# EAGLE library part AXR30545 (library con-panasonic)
AXR30545 Plug (Board mounting type) B type Source: http://www.panasonic-electric-works.ch/home/www/catalogues/connector/download/en_ds_65201_0000.pdf
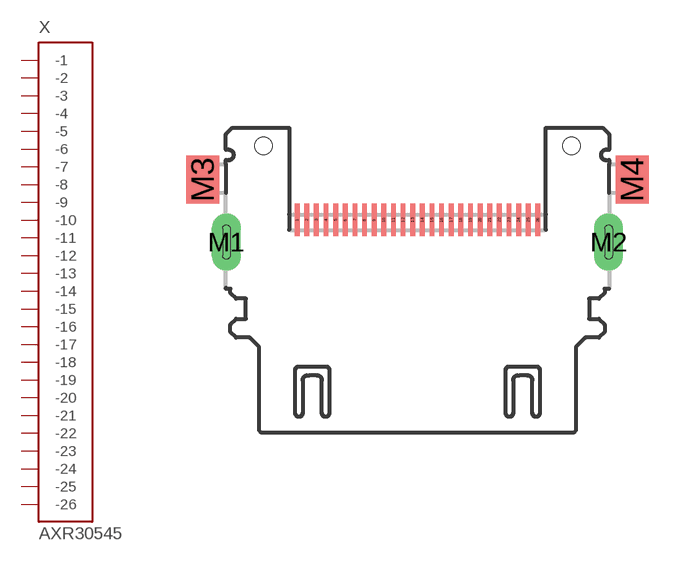
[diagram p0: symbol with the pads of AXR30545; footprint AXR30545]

Designator prefix X

## AXR30545  [AXR30545]
1  -1  in
2  -2  in
3  -3  in
4  -4  in
5  -5  in
6  -6  in
7  -7  in
8  -8  in
9  -9  in
10  -10  in
11  -11  in
12  -12  in
13  -13  in
14  -14  in
15  -15  in
16  -16  in
17  -17  in
18  -18  in
19  -19  in
20  -20  in
21  -21  in
22  -22  in
23  -23  in
24  -24  in
25  -25  in
26  -26  in

## Footprint AXR30545 (pad centres in mm)
AXR30545 Connector Source: http://www.panasonic-electric-works.ch/home/www/catalogues/connector/download/en_ds_65201_0000.pdf
smd 0.25 x 1.7: 1 -6.25,1.15; 2 -5.75,1.15; 3 -5.25,1.15; 4 -4.75,1.15; 5 -4.25,1.15; 6 -3.75,1.15; 7 -3.25,1.15; 8 -2.75,1.15; 9 -2.25,1.15; 10 -1.75,1.15; 11 -1.25,1.15; 12 -0.75,1.15; 13 -0.25,1.15; 14 0.25,1.15; 15 0.75,1.15; 16 1.25,1.15; 17 1.75,1.15; 18 2.25,1.15; 19 2.75,1.15; 20 3.25,1.15; 21 3.75,1.15; 22 4.25,1.15; 23 4.75,1.15; 24 5.25,1.15; 25 5.75,1.15; 26 6.25,1.15
drill 0.4 pad 1.5 long: M1 -9.925,0; M2 9.925,0
smd 1.7 x 2.5: M3 -11.15,3.25; M4 11.15,3.25
hole 0.9 at -8,5
hole 0.9 at 8,5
